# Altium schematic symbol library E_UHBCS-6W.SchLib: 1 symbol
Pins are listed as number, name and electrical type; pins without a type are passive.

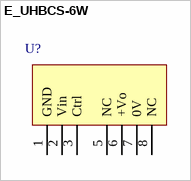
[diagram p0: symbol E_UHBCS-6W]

## E_UHBCS-6W
designator U?
footprint E_UHBCS-6W
pins: 1 GND, 2 Vin, 3 Ctrl, 5 NC, 6 +Vo, 7 0V, 8 NC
